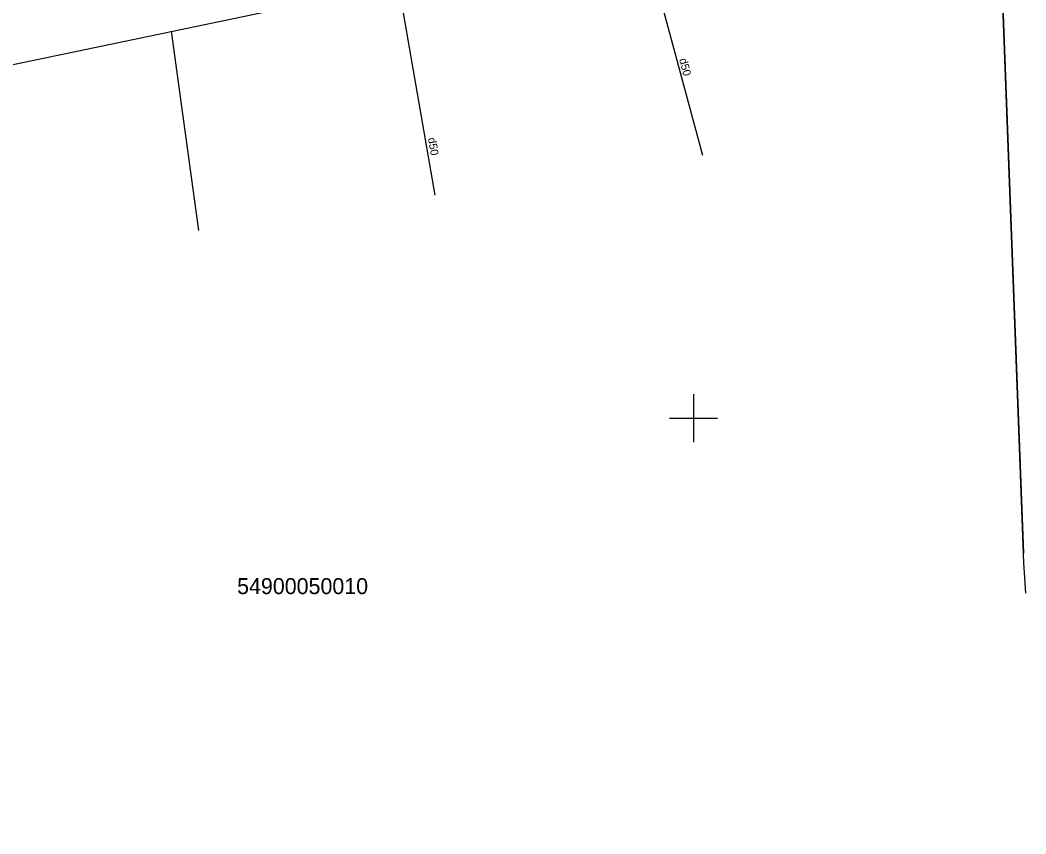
# Model space of a CAD drawing. Extents: x 469981 to 472086, y 246785 to 247785.
# Drawn here: x 471907.9 to 471970.8, y 247574 to 247624.9 of the extents above; entities that cross this region are included whole.
import ezdxf

# ---------------------------------------------------------------- set-up
doc = ezdxf.new("R2010")
doc.units = 0
for name, color, linetype in [('DREN_VADP_####_####_#', 7, 'Continuous'), ('DREN_VADP_####_TKST_#', 7, 'Continuous'), ('DREN_VADP_KLKT_####_#', 7, 'Continuous'), ('GEOD_ELEM_####_####_#', 7, 'Continuous'), ('ROBZ_IERR_####_####_#', 7, 'Continuous'), ('ROBZ_IERR_####_TKST_#', 7, 'Continuous'), ('ROBZ_PROJ_####_####_#', 7, 'Continuous')]:
    doc.layers.add(name, color=color, linetype=linetype)

msp = doc.modelspace()

# ---------------------------------------------------------------- linework, layer by layer
at = {"layer": 'DREN_VADP_####_####_#'}
for points in [[(471946.806, 247630.31), (471950.555, 247616.428)], [(471933.87, 247613.932), (471931.579, 247627.132)], [(471917.383, 247624.168), (471919.079, 247611.719)]]:
    msp.add_lwpolyline(points, dxfattribs=at)
at = {"layer": 'DREN_VADP_KLKT_####_#'}
msp.add_lwpolyline([(471872.545, 247614.805), (471946.806, 247630.31)], dxfattribs=at)
at = {"layer": 'GEOD_ELEM_####_####_#'}
for p, q in [((471950, 247601.5), (471950, 247600)), ((471948.5, 247600), (471950, 247600)), ((471950, 247600), (471950, 247598.5)), ((471950, 247600), (471951.5, 247600))]:
    msp.add_line(p, q, dxfattribs=at)
at = {"layer": 'ROBZ_IERR_####_####_#'}
msp.add_lwpolyline([(471879.163, 247574.024), (471880.66, 247583.5), (471867.531, 247625.725), (471968.24, 247654.462), (471970.607, 247591.56)], dxfattribs=at)
at = {"layer": 'ROBZ_PROJ_####_####_#'}
msp.add_lwpolyline([(471970.761, 247589.071), (471970.63, 247590.953), (471968.24, 247654.462), (471968.166, 247666.92), (471968.725, 247708.744)], dxfattribs=at)
msp.add_lwpolyline([(471970.761, 247589.071), (471970.63, 247590.953), (471968.24, 247654.462), (471968.166, 247666.92), (471968.725, 247708.744)], dxfattribs=at)

# ---------------------------------------------------------------- texts
at = {"layer": 'DREN_VADP_####_TKST_#'}
for rotation, p in [(285.11223, (471949.097, 247622.401)), (279.84806, (471933.408, 247617.473))]:
    msp.add_text('d50', height=0.5, rotation=rotation, dxfattribs=at).set_placement(p)
at = {"layer": 'ROBZ_IERR_####_TKST_#'}
msp.add_text('54900050010', height=1, dxfattribs=at).set_placement((471921.493, 247589.001))

doc.saveas('drawing.dxf')
